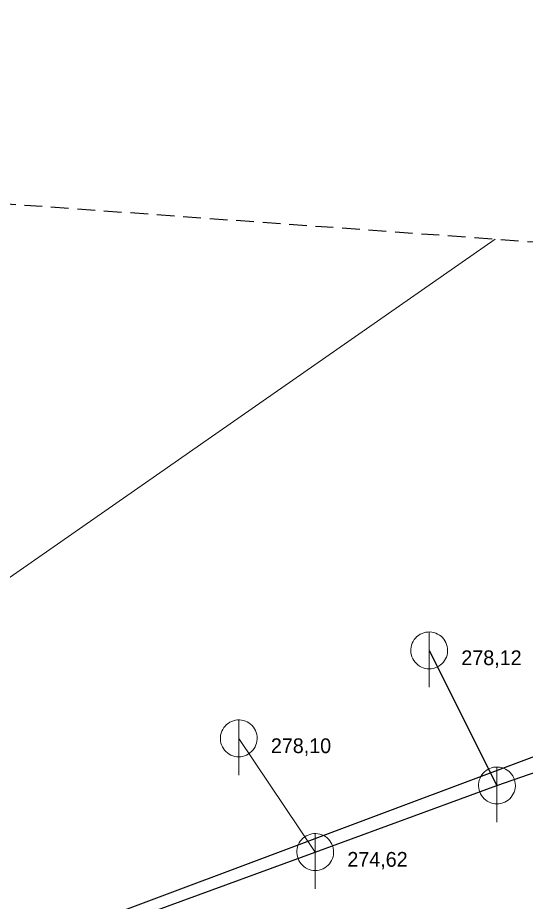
# Model space of a CAD drawing. Extents: x -725153 to -724843, y -978146 to -977794.
# Drawn here: x -724985.66 to -724958.1, y -977842.4 to -977794.45 of the extents above; entities that cross this region are included whole.
import ezdxf

# ---------------------------------------------------------------- set-up
doc = ezdxf.new("R2010")
doc.units = 0
doc.header["$LTSCALE"] = 0.32
doc.linetypes.add('MEDIUM_DASHED', pattern=[4.5, 3, -1.5])
for name, color, linetype, lineweight in [('11', 7, 'Continuous', 13), ('13', 7, 'Continuous', 13), ('14', 7, 'Continuous', 25), ('22', 7, 'Continuous', 13), ('63', 7, 'MEDIUM_DASHED', 25)]:
    doc.layers.add(name, color=color, linetype=linetype, lineweight=lineweight)

msp = doc.modelspace()

# ---------------------------------------------------------------- linework, layer by layer
at = {"layer": '11'}
msp.add_line((-724969.506, -977839.725), (-724973.658, -977833.557), dxfattribs=at)
at = {"layer": '13'}
msp.add_line((-724959.747, -977806.461), (-724988.359, -977826.402), dxfattribs=at)
at = {"layer": '14'}
for p, q in [((-724983.75, -977844.32), (-724941.885, -977828.658)), ((-724963.322, -977828.784), (-724959.646, -977836.111)), ((-724959.646, -977836.111), (-724945.344, -977831.146))]:
    msp.add_line(p, q, dxfattribs=at)
msp.add_lwpolyline([(-724985.54, -977845.6), (-724969.507, -977839.725), (-724959.646, -977836.111)], dxfattribs=at)
at = {"layer": '22'}
for p, q in [((-724963.322, -977830.784), (-724963.321, -977827.784)), ((-724973.658, -977835.558), (-724973.657, -977832.558)), ((-724959.646, -977838.111), (-724959.645, -977835.111)), ((-724969.507, -977841.725), (-724969.506, -977838.725))]:
    msp.add_line(p, q, dxfattribs=at)
for points in [[(-724962.322, -977828.784), (-724962.327, -977828.675), (-724962.345, -977828.567), (-724962.375, -977828.461), (-724962.415, -977828.36), (-724962.467, -977828.263), (-724962.529, -977828.173), (-724962.601, -977828.09), (-724962.681, -977828.016), (-724962.769, -977827.95), (-724962.863, -977827.895), (-724962.963, -977827.85), (-724963.068, -977827.817), (-724963.175, -977827.795), (-724963.284, -977827.785), (-724963.394, -977827.787), (-724963.502, -977827.801), (-724963.609, -977827.826), (-724963.712, -977827.863), (-724963.81, -977827.912), (-724963.902, -977827.97), (-724963.988, -977828.039), (-724964.065, -977828.116), (-724964.134, -977828.202), (-724964.193, -977828.294), (-724964.241, -977828.392), (-724964.278, -977828.495), (-724964.304, -977828.602), (-724964.318, -977828.71), (-724964.321, -977828.82), (-724964.311, -977828.929), (-724964.29, -977829.036), (-724964.256, -977829.14), (-724964.212, -977829.24), (-724964.157, -977829.335), (-724964.091, -977829.423), (-724964.017, -977829.503), (-724963.934, -977829.575), (-724963.844, -977829.637), (-724963.748, -977829.689), (-724963.646, -977829.73), (-724963.541, -977829.76), (-724963.433, -977829.778), (-724963.323, -977829.784), (-724963.214, -977829.778), (-724963.106, -977829.76), (-724963.001, -977829.731), (-724962.899, -977829.69), (-724962.802, -977829.638), (-724962.712, -977829.576), (-724962.629, -977829.505), (-724962.554, -977829.425), (-724962.489, -977829.337), (-724962.433, -977829.243), (-724962.389, -977829.143), (-724962.355, -977829.039), (-724962.333, -977828.931), (-724962.323, -977828.822)], [(-724972.658, -977833.558), (-724972.663, -977833.449), (-724972.681, -977833.341), (-724972.711, -977833.235), (-724972.751, -977833.134), (-724972.803, -977833.037), (-724972.865, -977832.947), (-724972.937, -977832.864), (-724973.017, -977832.79), (-724973.105, -977832.724), (-724973.199, -977832.669), (-724973.299, -977832.624), (-724973.404, -977832.591), (-724973.511, -977832.569), (-724973.62, -977832.559), (-724973.73, -977832.561), (-724973.838, -977832.575), (-724973.945, -977832.6), (-724974.048, -977832.637), (-724974.146, -977832.686), (-724974.238, -977832.744), (-724974.324, -977832.813), (-724974.401, -977832.89), (-724974.47, -977832.976), (-724974.529, -977833.068), (-724974.577, -977833.166), (-724974.614, -977833.269), (-724974.64, -977833.376), (-724974.654, -977833.484), (-724974.657, -977833.594), (-724974.647, -977833.703), (-724974.626, -977833.81), (-724974.592, -977833.914), (-724974.548, -977834.014), (-724974.493, -977834.109), (-724974.427, -977834.197), (-724974.353, -977834.277), (-724974.27, -977834.349), (-724974.18, -977834.411), (-724974.084, -977834.463), (-724973.982, -977834.504), (-724973.877, -977834.534), (-724973.769, -977834.552), (-724973.659, -977834.558), (-724973.55, -977834.552), (-724973.442, -977834.534), (-724973.337, -977834.505), (-724973.235, -977834.464), (-724973.138, -977834.412), (-724973.048, -977834.35), (-724972.965, -977834.279), (-724972.89, -977834.199), (-724972.825, -977834.111), (-724972.769, -977834.017), (-724972.725, -977833.917), (-724972.691, -977833.813), (-724972.669, -977833.705), (-724972.659, -977833.596)], [(-724958.646, -977836.111), (-724958.651, -977836.002), (-724958.669, -977835.894), (-724958.699, -977835.788), (-724958.739, -977835.687), (-724958.791, -977835.59), (-724958.853, -977835.5), (-724958.925, -977835.417), (-724959.005, -977835.343), (-724959.093, -977835.277), (-724959.187, -977835.222), (-724959.287, -977835.177), (-724959.392, -977835.144), (-724959.499, -977835.122), (-724959.608, -977835.112), (-724959.718, -977835.114), (-724959.826, -977835.128), (-724959.933, -977835.153), (-724960.036, -977835.19), (-724960.134, -977835.239), (-724960.226, -977835.297), (-724960.312, -977835.366), (-724960.389, -977835.443), (-724960.458, -977835.529), (-724960.517, -977835.621), (-724960.565, -977835.719), (-724960.602, -977835.822), (-724960.628, -977835.929), (-724960.642, -977836.037), (-724960.645, -977836.147), (-724960.635, -977836.256), (-724960.614, -977836.363), (-724960.58, -977836.467), (-724960.536, -977836.567), (-724960.481, -977836.662), (-724960.415, -977836.75), (-724960.341, -977836.83), (-724960.258, -977836.902), (-724960.168, -977836.964), (-724960.072, -977837.016), (-724959.97, -977837.057), (-724959.865, -977837.087), (-724959.757, -977837.105), (-724959.647, -977837.111), (-724959.538, -977837.105), (-724959.43, -977837.087), (-724959.325, -977837.058), (-724959.223, -977837.017), (-724959.126, -977836.965), (-724959.036, -977836.903), (-724958.953, -977836.832), (-724958.878, -977836.752), (-724958.813, -977836.664), (-724958.757, -977836.57), (-724958.713, -977836.47), (-724958.679, -977836.366), (-724958.657, -977836.258), (-724958.647, -977836.149)], [(-724968.507, -977839.725), (-724968.512, -977839.616), (-724968.53, -977839.508), (-724968.56, -977839.402), (-724968.6, -977839.301), (-724968.652, -977839.204), (-724968.714, -977839.114), (-724968.786, -977839.031), (-724968.866, -977838.957), (-724968.954, -977838.891), (-724969.048, -977838.836), (-724969.148, -977838.791), (-724969.253, -977838.758), (-724969.36, -977838.736), (-724969.469, -977838.726), (-724969.579, -977838.728), (-724969.687, -977838.742), (-724969.794, -977838.767), (-724969.897, -977838.804), (-724969.995, -977838.853), (-724970.087, -977838.911), (-724970.173, -977838.98), (-724970.25, -977839.057), (-724970.319, -977839.143), (-724970.378, -977839.235), (-724970.426, -977839.333), (-724970.463, -977839.436), (-724970.489, -977839.543), (-724970.503, -977839.651), (-724970.506, -977839.761), (-724970.496, -977839.87), (-724970.475, -977839.977), (-724970.441, -977840.081), (-724970.397, -977840.181), (-724970.342, -977840.276), (-724970.276, -977840.364), (-724970.202, -977840.444), (-724970.119, -977840.516), (-724970.029, -977840.578), (-724969.933, -977840.63), (-724969.831, -977840.671), (-724969.726, -977840.701), (-724969.618, -977840.719), (-724969.508, -977840.725), (-724969.399, -977840.719), (-724969.291, -977840.701), (-724969.186, -977840.672), (-724969.084, -977840.631), (-724968.987, -977840.579), (-724968.897, -977840.517), (-724968.814, -977840.446), (-724968.739, -977840.366), (-724968.674, -977840.278), (-724968.618, -977840.184), (-724968.574, -977840.084), (-724968.54, -977839.98), (-724968.518, -977839.872), (-724968.508, -977839.763)]]:
    msp.add_lwpolyline(points, close=True, dxfattribs=at)
at = {"layer": '63'}
msp.add_lwpolyline([(-725126.038, -977904.704), (-725126.038, -977794.451), (-724874.829, -977812.594), (-724855.29, -977827.945), (-724842.73, -977919.358), (-724859.477, -977998.21), (-724911.114, -978092.413), (-724961.356, -978146.144), (-725152.554, -978126.605)], close=True, dxfattribs=at)

# ---------------------------------------------------------------- texts
at = {"layer": '22'}
for s, p in [('278,12', (-724961.579, -977829.583)), ('278,10', (-724971.915, -977834.358)), ('274,62', (-724967.764, -977840.524))]:
    msp.add_text(s, height=0.8, dxfattribs=at).set_placement(p)

doc.saveas('drawing.dxf')
